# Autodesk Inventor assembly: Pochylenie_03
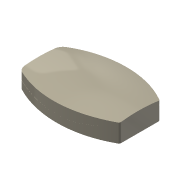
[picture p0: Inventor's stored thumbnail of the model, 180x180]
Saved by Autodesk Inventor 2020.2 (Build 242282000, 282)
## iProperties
Manager: www.cadconsulting.pl
Company: Fabian Stasiak CAD Consulting
Created: 2005-05
Part Number: Pochylenie_03
Document SubType Name: Assembly
Designer: F.Stasiak
Manufacturer: Standard
Standards Organization: Custom
Author: F.Stasiak
Subject: Zbiór ćwiczeń. Autodesk Inventor 2020. Kurs podstawowy
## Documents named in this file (3)
- C:\2020_Kurs_podstawowy\R5 Części\Elementy\Pochylenie_03.iam
- C:\2020_Kurs_podstawowy\R5 Części\Elementy\Pochylenie_03_B.ipt
- C:\2020_Kurs_podstawowy\R5 Części\Elementy\Pochylenie_03_A.ipt
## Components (2 placed, 2 different names)
1. Pochylenie_03_B:1 — Równoległy:1, Równoległy:2, Równoległy:3
2. Pochylenie_03_A:1 — Równoległy:1, Równoległy:2, Równoległy:3
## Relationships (3: Flush 3)
- Równoległy:1 [Flush]: Pochylenie_03_B:1 ↔ Pochylenie_03_A:1
- Równoległy:2 [Flush]: Pochylenie_03_B:1 ↔ Pochylenie_03_A:1
- Równoległy:3 [Flush]: Pochylenie_03_B:1 ↔ Pochylenie_03_A:1
